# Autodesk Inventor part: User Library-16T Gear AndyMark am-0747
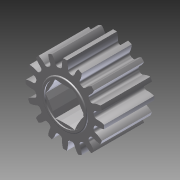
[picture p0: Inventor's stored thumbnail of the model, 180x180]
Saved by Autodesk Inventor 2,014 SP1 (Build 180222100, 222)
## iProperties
Created: 2014-11
Part Number: User Library-16T Gear AndyMark am-0747
Material: Aluminum 6061
Document SubType Name: Modeling
Designer: Michael
Density: 2.71 g/cm^3
Appearance: Aluminum - Flat
Author: Windows User
Title: User Library-16T Gear AndyMark am-0747.STEP
Description: STEP AP214
Creation Date: 2014-11-06
Sending System: SolidWorks 2014
Preprocessor: SwSTEP 2.0
Author: Michael
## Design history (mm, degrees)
node "User Library-16T Gear AndyMark am-07471"
sketch "Sketch1"
  geometry: L1 (-12.109, 17.144)-(-11.449, 14.364); L2 (-11.56, 17.26)-(-10.739, 17.668); L3 (-10.739, 17.668)-(-10.049, 14.759); L4 (-10.049, 14.759)-(-10.006, 14.579); L5 (-12.912, 13.874)-(-13.694, 17.17); L6 (-13.694, 17.17)-(-12.651, 17.001); L7 (-11.56, 17.26)-(-10.739, 17.668); L8 (-10.739, 17.668)-(-10.006, 14.579); A1 r 8.573 centre (-9.469, 6.023) between (-9.363, 14.595) and (-10.204, 14.564) reference; A2 r 11.43 centre (-9.469, 6.023) between (-11.56, 17.26) and (-12.651, 17.001) reference; A3 r 8.573 centre (-9.469, 6.023) between (-12.651, 13.983) and (-13.416, 13.633) reference; A4 r 5 centre (-7.686, 16.413) between (-12.651, 17.001) and (-12.152, 14.165); A5 r 8.573 centre (-9.469, 6.023) between (-9.363, 14.595) and (-13.416, 13.633); A6 r 5 centre (-15.731, 14.504) between (-10.731, 14.502) and (-11.56, 17.26); A7 r 5 centre (-15.731, 14.504) between (-10.731, 14.502) and (-11.56, 17.26); A8 r 8.572 centre (-9.469, 6.023) between (-10.006, 14.579) and (-10.731, 14.502)
  constraints: 17 point on circle, 16 end point, 5 centre point, 2 collinear, 2 parallel, 2 symmetric about line, 1 concentric, 1 other
  dimensions: "d0" = 5 radius of A4
extrude "Extrusion1" cut sketch "Sketch1" stored distance "d1" = 10; taper "d2" = 0 deg
pattern_circular "Circular Pattern1" dims angle "d4" = 360 deg
fillet "Fillet1" dims "d6" = 0.79375
pattern_circular "Circular Pattern2" dims angle "d8" = 360 deg
body "Solid1"
node "Base1"
